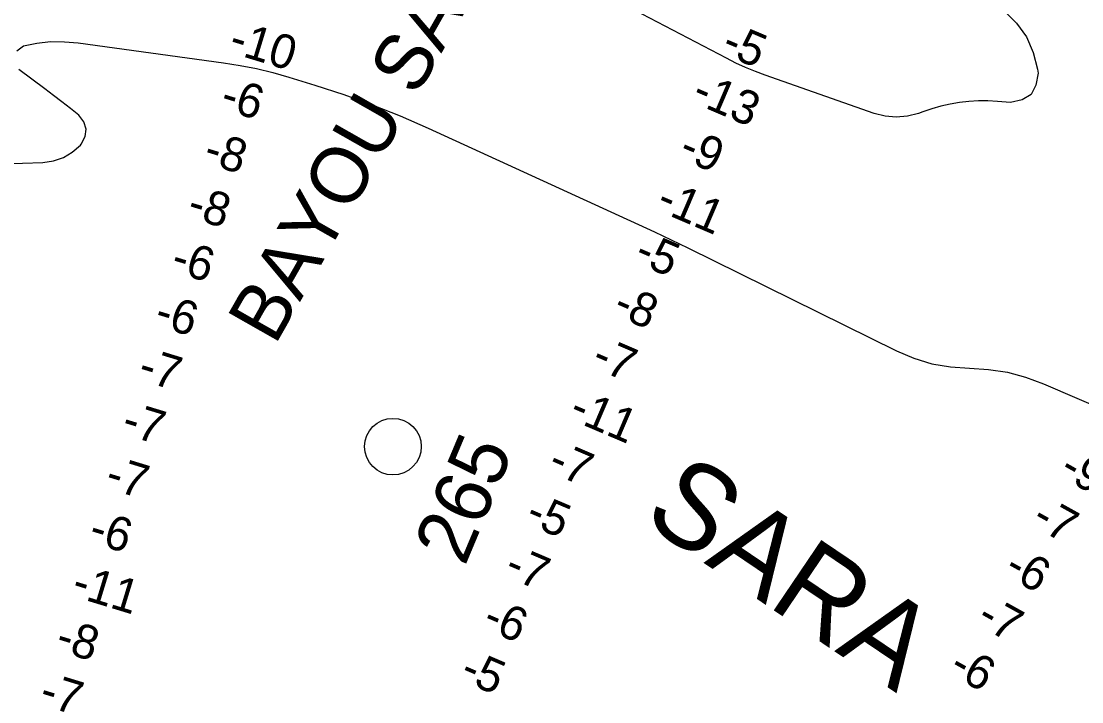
# Model space of a CAD drawing. Extents: x 3245246 to 3283090, y 806824 to 832173.
# Drawn here: x 3265543 to 3267417, y 820567 to 821769 of the extents above; entities that cross this region are included whole.
import ezdxf

# ---------------------------------------------------------------- set-up
doc = ezdxf.new("R2010")
doc.units = 0
for name, color, linetype in [('V-CHAN-NAID', 7, 'Continuous'), ('V-RIVR-IDEN', 7, 'Continuous'), ('V-RIVR-MILE', 7, 'Continuous'), ('V-RIVR-RANG', 7, 'Continuous'), ('V-ROAD-CNTR', 7, 'Continuous'), ('V-TOPO-MINR', 7, 'Continuous')]:
    doc.layers.add(name, color=color, linetype=linetype)

msp = doc.modelspace()

# ---------------------------------------------------------------- linework, layer by layer
at = {"layer": 'V-RIVR-MILE'}
msp.add_circle((3266200, 821017.6), 50, dxfattribs=at)
at = {"layer": 'V-ROAD-CNTR'}
msp.add_spline([(3265843.1, 823432.9), (3265859, 823417.1), (3265884.4, 823393.5), (3265921.6, 823385.9), (3265988.6, 823351.1), (3266047.2, 823332.3), (3266110.9, 823317.7), (3266174.6, 823302.5), (3266237.9, 823256.1), (3266319, 823213.7), (3266446.2, 823144), (3266598.2, 823070.2), (3266698.3, 823024.2), (3266809.8, 822977.5), (3266902.8, 822954.7), (3266981.5, 822929.4), (3267047, 822922.9), (3267126.7, 822927), (3267196.8, 822934.5), (3267240.8, 822931.2), (3267315.5, 822929), (3267389.5, 822902.9), (3267472.5, 822855.3), (3267548.2, 822799.1), (3267673.2, 822703.2), (3267729.5, 822659.2), (3267800.8, 822580), (3267841.6, 822514.8), (3267890.4, 822443.6), (3267961.5, 822390.3), (3268026.2, 822347.9), (3268097.5, 822313.7), (3268226.8, 822221.5), (3268328.9, 822136.2), (3268438, 822030.2), (3268539.6, 821913.7), (3268611.4, 821855), (3268669.7, 821833), (3268741.6, 821835.2), (3268781, 821862.3), (3268824.2, 821916.6), (3268873.1, 822006.3), (3268932.5, 822098.1), (3268972.1, 822145.5), (3269019.4, 822162), (3269056, 822158.3), (3269086.7, 822138.7), (3269215.7, 821995.6), (3269467.1, 821682.5), (3269665, 821425.3), (3269890.2, 821132.3), (3269935.6, 821060.8), (3269937.8, 820947), (3269911.9, 820878.4), (3269882.4, 820803.4), (3269850.4, 820754.7), (3269820.8, 820702.9), (3269847.5, 820661.4), (3269995.3, 820504.9), (3270135.1, 820342.3), (3270215.8, 820249.2), (3270280.9, 820161.5), (3270409.8, 819983.2), (3270585.2, 819734.7), (3270723.1, 819531.2), (3270847.8, 819342.2), (3270941.2, 819194.9), (3271024.2, 819065), (3271103.7, 818956), (3271217.9, 818809.2), (3271322.1, 818665), (3271450.9, 818481.1), (3271547.8, 818329.9), (3271656.2, 818159), (3271778.9, 817965.4), (3271939, 817707.5), (3272036.6, 817466.5), (3272126.7, 817285.3), (3272211.9, 817051.1), (3272318, 816867.5), (3272429.4, 816683.2), (3272508.6, 816556.2), (3272571.6, 816398.7), (3272670.4, 816197), (3272779.9, 816022.9), (3272872.1, 815803.2), (3272964.7, 815556.6)], degree=3, dxfattribs=at)
at = {"layer": 'V-TOPO-MINR'}
for points in [[(3267279.7, 821787.5), (3267301.4, 821765.8), (3267319.1, 821741.8), (3267330.8, 821714.3), (3267338.4, 821684.6), (3267339.4, 821677.3), (3267335.8, 821656.3), (3267327.3, 821639.9), (3267311.3, 821630.5), (3267290.5, 821625.9), (3267267.6, 821627.8), (3267250.9, 821628.6), (3267234.1, 821628.6), (3267217.4, 821627.5), (3267200.7, 821625.6), (3267184.2, 821622.7), (3267167.8, 821619.1), (3267151.7, 821614.5), (3267135.7, 821609.3), (3267128.3, 821606.6), (3267108.7, 821601.7), (3267089.1, 821599.6), (3267069.5, 821601.6), (3267049.9, 821606.3), (3266857.6, 821673.9), (3266840.1, 821680.5), (3266822.8, 821687.6), (3266805.8, 821695.4), (3266789, 821703.8), (3266612.9, 821795.8)], [(3265535.9, 821717.1), (3265547.2, 821725.8), (3265571.2, 821730.5), (3265595.3, 821733.3), (3265619.6, 821733.2), (3265644, 821731.3), (3265901, 821696), (3265930.1, 821691.3), (3265959, 821685.6), (3265987.7, 821678.6), (3266016.1, 821670.7), (3266062.1, 821656.6), (3266113, 821639.9), (3266163.3, 821621.9), (3266213, 821601.9), (3266262.1, 821580.5), (3266661.9, 821397), (3266676.7, 821390.2), (3266691.4, 821383.2), (3266706.1, 821376.2), (3266720.7, 821369), (3267089.2, 821186.7), (3267120.3, 821173.9), (3267152.1, 821164), (3267184.9, 821158.5), (3267218.4, 821156), (3267252.1, 821153.7), (3267285.2, 821148.9), (3267317.4, 821140.1), (3267349.2, 821128.6), (3267470.9, 821076.4)], [(3265507.5, 821518.1), (3265545.4, 821518.7), (3265581.6, 821519.9), (3265600.3, 821522.8), (3265617.9, 821528.5), (3265633.6, 821538.2), (3265648, 821550.5), (3265649.3, 821551.9), (3265656.1, 821565.4), (3265658.4, 821578.6), (3265654, 821591.3), (3265645.1, 821603.5), (3265630.3, 821615.2), (3265615.3, 821626.9), (3265600.2, 821638.3), (3265585.1, 821649.7), (3265539, 821684)]]:
    msp.add_lwpolyline(points, dxfattribs=at)

# ---------------------------------------------------------------- texts
at = {"layer": 'V-CHAN-NAID'}
msp.add_text('BAYOU SARA BEND (264.8)', height=100, rotation=60.3849, dxfattribs=at).set_placement((3265991.5, 821195))
at = {"layer": 'V-RIVR-IDEN'}
for s, height, rotation, p in [('265', 100, 67.2413, (3266326.8, 820804.7)), ('SARA', 150, 325.936, (3266637.3, 820887.4))]:
    msp.add_text(s, height=height, rotation=rotation, dxfattribs=at).set_placement(p)
at = {"layer": 'V-RIVR-RANG'}
for s, rotation, p in [('-10', 343.0459, (3265907.5, 821715.2)), ('-5', 336.8822, (3266777.4, 821713.7)), ('-6', 343.0459, (3265892.3, 821615.3)), ('-13', 336.8822, (3266725, 821627.3)), ('-8', 343.0459, (3265862.8, 821519.8)), ('-9', 336.8822, (3266702, 821528.4)), ('-11', 336.8822, (3266662.2, 821436.7)), ('-8', 343.0459, (3265833.7, 821424.1)), ('-5', 336.8822, (3266623.5, 821344.5)), ('-6', 343.0459, (3265805.1, 821328.3)), ('-8', 336.8822, (3266585.9, 821251.8)), ('-6', 343.0459, (3265776.1, 821232.6)), ('-7', 336.8822, (3266547.9, 821159.3)), ('-7', 343.0459, (3265747, 821136.9)), ('-11', 336.8822, (3266508.3, 821067.5)), ('-7', 343.0459, (3265718, 821041.2)), ('-7', 336.8822, (3266470.9, 820974.7)), ('-7', 343.0459, (3265688.9, 820945.5)), ('-9', 330.8837, (3267374.2, 820966.8)), ('-5', 336.8822, (3266431.1, 820883)), ('-7', 330.8837, (3267325.3, 820879.6)), ('-6', 343.0459, (3265659.9, 820849.8)), ('-7', 336.8822, (3266394, 820790.1)), ('-6', 330.8837, (3267276.6, 820792.2)), ('-11', 343.0459, (3265629.7, 820754.5)), ('-7', 330.8837, (3267228, 820704.8)), ('-6', 336.8822, (3266355.5, 820697.8)), ('-8', 343.0459, (3265601.3, 820658.6)), ('-5', 336.8822, (3266315.7, 820606.1)), ('-6', 330.8837, (3267179.3, 820617.5)), ('-7', 343.0459, (3265572.7, 820562.8))]:
    msp.add_text(s, height=60, rotation=rotation, dxfattribs=at).set_placement(p)

doc.saveas('drawing.dxf')
